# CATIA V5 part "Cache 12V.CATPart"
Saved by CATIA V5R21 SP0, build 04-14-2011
Part number: Cache 12V
Bounding box of the stored display mesh (mm): x -84 to 0, y -19.2 to 9, z 0 to 12
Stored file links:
  C:\Users\zerma\Pictures\Perso\Cache 12V.CATPart
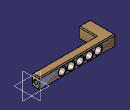
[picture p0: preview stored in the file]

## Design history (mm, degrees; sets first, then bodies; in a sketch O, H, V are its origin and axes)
Body1 (main body)
  Sketch1 on xy-plane, origin (0, 0, 0), H (1, 0, 0), V (0, 1, 0)
    line L1 (-84, 9) -> (0, 9)
    line L2 (0, 9) -> (0, 0)
    line L3 (0, 0) -> (-84, 0)
    line L4 (-84, 0) -> (-84, 9)
    length L2 = 9
    length L1 = 84
    horizontal: L1 H, L3 H
    vertical: L2 V, L4 V
  Pad1: profile Sketch1, direction (0, 0, 1), length 12
  Sketch2 on face of Pad1 from Sketch1.L3, origin (0, 0, 0), H (1, 0, 0), V (0, 0, 1)
    line L1 (-84, 0) -> (-71, 0)
    line L2 (-71, 0) -> (-71, 12)
    line L3 (-71, 12) -> (-84, 12)
    line L4 (-84, 12) -> (-84, 0)
    reference projected line E1 (-84, 12) -> (0, 12) from edge [face of Pad1 from Sketch1.L3 | end face of Pad1]
    reference projected line E2 (-84, 0) -> (-84, 12) from edge [face of Pad1 from Sketch1.L3 | face of Pad1 from Sketch1.L4]
    reference projected line E3 (-84, 0) -> (0, 0) from edge [start face of Pad1 | face of Pad1 from Sketch1.L3]
    distance L2 L4 = 13
    horizontal: L1 H, L3 H
    vertical: L2 V, L4 V
    coincidence: L3 E1, L4 E2, L1 E3
  Pad2: profile Sketch2, direction (0, -1, 0), length 19.2
  Sketch3 on face of Pad1 from Sketch1.L2, origin (0, 0, 0), H (0, 1, 0), V (0, 0, 1)
    circle A1 centre (4.5, 6) radius 1.95
    point P1 (4.5, 6)
    reference projected line E1 (0, 0) -> (0, 12) from edge [face of Pad1 from Sketch1.L2 | face of Pad1 from Sketch1.L3]
    radius A1 = 1.95
    distance P1 H = 6
    distance P1 E1 = 4.5
  Pocket1: profile Sketch3, direction (-1, 0, 0), length 8
  Sketch4 on end face of Pad2, origin (0, -19.2, 0), H (1, 0, 0), V (0, 0, 1)
    circle A1 centre (-75, 6) radius 1.95
    point P1 (-75, 6)
    reference projected line E1 (-71, 0) -> (-71, 12) from edge [face of Pad2 from Sketch2.L2 | end face of Pad2]
    reference projected line E2 (-84, 0) -> (-71, 0) from edge [face of Pad2 | end face of Pad2]
    radius A1 = 1.95
    distance P1 E1 = 4
    distance P1 E2 = 6
  Pocket2: profile Sketch4, direction (0, 1, 0), length 8
  Chamfer1: length 0.4, angle 45, on edge [face of Pad1 from Sketch1.L2 | face of Pocket1 from Sketch3.A1]; edge [end face of Pad2 | face of Pocket2 from Sketch4.A1]
  Sketch5 on face of Pad1 from Sketch1.L3, origin (0, 0, 0), H (1, 0, 0), V (0, 0, 1)
    circle A1 centre (-65, 6) radius 4
    point P1 (-65, 6)
    reference projected line E1 (-84, 12) -> (0, 12) from edge [face of Pad1 from Sketch1.L3 | face of Pad2]
    reference projected line E2 (-71, 0) -> (-71, 12) from edge [face of Pad2 from Sketch2.L2 | end face of Pad2]
    radius A1 = 4
    distance P1 E1 = 6
    distance P1 E2 = 6
  Pocket3: profile Sketch5, direction (0, 1, 0), length 19.2
  RectPattern1: of Pocket3, direction 1 instances 5, spacing 10, along edge [face of Pad2 | face of Pad1 from Sketch1.L3]
  Chamfer2: length 1, angle 45, on edge [face of Pad1 from Sketch1.L1 | face of Pad2]; edge [face of Pad2 | face of Pad2] (x2); edge [face of Pad2 | face of Pad1 from Sketch1.L1] (x2); edge [face of Pad2 | end face of Pad2] (x3); edge [face of Pad2 | face of Pad2 from Sketch2.L2]; edge [face of Pad1 from Sketch1.L3 | face of Pad2]; edge [face of Pad1 from Sketch1.L1 | face of Pad1 from Sketch1.L2]; edge [face of Pad2 | face of Pad1 from Sketch1.L3]; edge [face of Pad1 from Sketch1.L2 | face of Pad1 from Sketch1.L3]; edge [face of Pad2 | face of Pad1 from Sketch1.L2]; edge [face of Pad1 from Sketch1.L2 | face of Pad2]; edge [face of Pad2 from Sketch2.L2 | end face of Pad2]; edge [face of Pad2 from Sketch2.L2 | face of Pad2]
  Fillet1: radius 1, on edge [face of Pad1 from Sketch1.L3 | face of Pad2 from Sketch2.L2]
  Chamfer3: length 0.5, angle 45, on edge [face of RectPattern1 | face of Pad1 from Sketch1.L1] (x4); edge [face of Pocket3 from Sketch5.A1 | face of Pad1 from Sketch1.L1]; edge [face of Pad1 from Sketch1.L3 | face of RectPattern1]; face of RectPattern1 (x3); edge [face of Pad1 from Sketch1.L3 | face of Pocket3 from Sketch5.A1]
  CLDGeom1 "Maillage.1"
